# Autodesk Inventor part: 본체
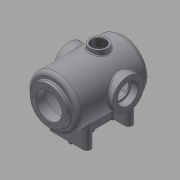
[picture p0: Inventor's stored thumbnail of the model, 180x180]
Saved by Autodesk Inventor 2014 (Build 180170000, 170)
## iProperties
Created: 2016-02
Part Number: 본체
Material: Aluminum 6061
Document SubType Name: Modeling
Designer: mduedu
Density: 2.71 g/cm^3
Appearance: Default
Mass: 3178.08 g
Surface Area: 2086.6 cm^2
Volume: 1172.72 cm^3
Author: mduedu
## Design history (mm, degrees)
sketch "스케치2"
  geometry: L1 (0, 100)-(0, -100); L2 (65, -75.993)-(65, 100); L3 (65, 100)-(0, 100); A1 r 100 centre (0, 0) between (0, -100) and (65, -75.993); 2 further points
  constraints: 6 end point, 2 midpoint, 2 point on circle, 1 centre point, 1 coincident, 1 horizontal, 1 parallel, 1 vertical
  dimensions: "d3" = 200 distance of L1.start L1.end; "d5" = 130 diameter of L2 L1; "d6" = 100 radius of A1
revolve "회전1" sketch "스케치2" stored, may be unused: angle "d7" = 90 deg
sketch "스케치3"
  geometry: C1 r 47.5 at (0, 0); 1 further point
  constraints: 1 centre point, 1 coincident
  dimensions: "d8" = 95 diameter of C1
extrude "돌출2" join sketch "스케치3" distance "d10" = 10; taper "d11" = 0 deg
sketch "스케치5"
  geometry: L1 (47.5, 110)-(47.5, 100) reference; L2 (47.5, 100)-(65, 100) reference; L3 (65, 100)-(65, -75.993) reference; L4 (-65, -75.993)-(-65, 100) reference; L5 (-65, 100)-(-47.5, 100) reference; L6 (-47.5, 100)-(-47.5, 110) reference; L7 (-47.5, 110)-(47.5, 110) reference; L8 (55, 85)-(55, -71.239); L9 (0, 85)-(55, 85); L10 (0, 85)-(0, -90); A1 r 100 centre (0, 0) between (0, -100) and (65, -75.993) reference; A2 r 100 centre (0, 0) between (-65, -75.993) and (0, -100) reference; A3 r 90 centre (0, 0) between (0, -90) and (55, -71.239); 1 further point
  constraints: 6 end point, 2 point on circle, 1 centre point, 1 parallel, 1 perpendicular, 1 point on line, 1 vertical
  dimensions: "d13" = 10 distance between parallel lines of L3 L8; "d14" = 10 radial gap between concentric circles of A3 A1; "d15" = 15 distance between parallel lines of L9 L2
revolve "회전2" sketch "스케치5" stored, may be unused: angle "d16" = 90 deg
hole "구멍1" diameter "d19" = 65; stored, may be unused: countersink angle "d23" = 90 deg, drill point angle "d25" = 118 deg; dims "d17" = 10, "d18" = 10, "d20" = 6, "d21" = 4, "d22" = 2, "d24" = 8
node "작업 평면1"
sketch "스케치6"
  geometry: L1 (47.5, 110)-(-47.5, 110) reference; C1 r 40 at (0, -17); 1 further point
  constraints: 1 centre point, 1 vertical alignment
  dimensions: "d27" = 80 diameter of C1; "d29" = 127 distance from line of C1.centre L1
extrude "돌출3" join sketch "스케치6" stored distance "d30" = 10; taper "d31" = 0 deg
hole "구멍2" diameter "d34" = 42; stored, may be unused: countersink angle "d38" = 90 deg, drill point angle "d40" = 118 deg; dims "d32" = 10, "d33" = 10, "d35" = 6, "d36" = 52, "d37" = 18, "d39" = 8
sketch "스케치7" dims "d41" = 65
  geometry: C1 r 40 at (0, 0) reference; 3 further points
  constraints: 2 vertical alignment, 1 coincident, 2 other
hole "구멍3" sketch "스케치7" at (0, 32.5) diameter "d43" = 3.242; stored, may be unused: countersink angle "d47" = 90 deg, drill point angle "d49" = 118 deg; dims "d44" = 11, "d45" = 13, "d46" = 18, "d48" = 13
sketch "스케치8" dims "d53" = 80
  geometry: 3 further points
  constraints: 2 vertical alignment, 1 coincident, 2 other
hole "구멍4" sketch "스케치8" at (0, 40) diameter "d56" = 3.242; stored, may be unused: countersink angle "d60" = 90 deg, drill point angle "d62" = 118 deg; dims "d57" = 11, "d58" = 13, "d59" = 18, "d61" = 13
fillet "모깎기1" dims "d66" = 10
fillet "모깎기2" dims "d67" = 3
fillet "모깎기3" dims "d68" = 0.3
chamfer "모따기1" distance "d69" = 1; stored, may be unused: second distance "d70" = 2, angle "d71" = 45 deg
node "작업 평면5"
sketch "스케치10"
  geometry: L1 (-50, -63)-(50, -63); L2 (50, -63)-(50, -43); L3 (50, -43)-(-50, -43); L4 (-50, -43)-(-50, -63); L5 (-50, 0)-(50, 0); L6 (-50, 63)-(50, 63); L7 (50, 63)-(50, 43); L8 (50, 43)-(-50, 43); L9 (-50, 43)-(-50, 63); 2 further points
  constraints: 18 end point, 4 symmetric about line, 2 parallel, 2 perpendicular, 1 coincident, 1 horizontal, 1 midpoint
  dimensions: "d80" = 20 distance of L3.end L1.start; "d82" = 100 distance of L1.start L1.end; "d130" = 43 vertical distance of L3.end point (0, 0); "d131" = 50 horizontal distance of L3.end point (0, 0); "d132" = 100 distance of L5.start L5.end
extrude "돌출5" join sketch "스케치10" stored distance "d84" = 10; taper "d85" = 0 deg
sketch "스케치11"
  geometry: L1 (-100, -43)-(-100, 43); L2 (-65, 90)-(-65, -71.239) reference; L3 (-100, -43)-(-41.533, -43) reference; L4 (-100, 43)-(-41.533, 43) reference; 1 further point
  constraints: 2 end point, 1 point on line, 1 vertical
feature "리브1" sketch "스케치11" dims "d88" = 1, "d89" = 20, "d90" = 0, "d91" = 0, "d92" = 1, "d93" = 1
fillet "모깎기12"
fillet "모깎기13"
fillet "모깎기14"
fillet "모깎기15"
fillet "모깎기16" dims "d167" = 3
fillet "모깎기17" dims "d168" = 3
node "작업 평면6"
sketch "스케치19"
  geometry: L1 (75, -57)-(75, 23) reference; L2 (-75, -57)-(-75, 23) reference; L3 (75, -17)-(-75, -17); C1 r 22.5 at (0, -17); 1 further point
  constraints: 3 midpoint, 2 end point, 1 centre point
  dimensions: "d149" = 45 diameter of C1
extrude "돌출11" join sketch "스케치19" stored distance "d150" = 10; taper "d151" = 0 deg
hole "구멍6" diameter "d154" = 35; stored, may be unused: countersink angle "d158" = 90 deg, drill point angle "d160" = 118 deg; dims "d152" = 10, "d153" = 10, "d155" = 6, "d156" = 4, "d157" = 2, "d159" = 8
fillet "모깎기11" dims "d161" = 3
feature "스레드1" dims "d162" = 10, "d163" = 0
chamfer "모따기3" distance "d164" = 1; stored, may be unused: second distance "d165" = 2, angle "d166" = 45 deg
sketch "스케치20"
  geometry: L1 (10, 40)-(10, -40) reference; L2 (13, -43)-(40, -43) reference; L3 (40, -63)-(-40, -63) reference; L4 (-40, -43)-(-13, -43) reference; L5 (-10, -40)-(-10, 40) reference; L6 (-13, 43)-(-40, 43) reference; L7 (-40, 63)-(40, 63) reference; L8 (40, 43)-(13, 43) reference; L9 (-40, 53)-(40, 53); L10 (-40, -53)-(40, -53); L11 (0, 53)-(0, -53); C1 r 5 at (0, 53); C2 r 5 at (0, 0); C3 r 5 at (0, -53); A1 r 3 centre (13, -40) between (10, -40) and (13, -43) reference; A2 r 10 centre (40, -53) between (40, -63) and (40, -43) reference; A3 r 10 centre (-40, -53) between (-40, -43) and (-40, -63) reference; A4 r 3 centre (-13, -40) between (-13, -43) and (-10, -40) reference; A5 r 3 centre (-13, 40) between (-10, 40) and (-13, 43) reference; A6 r 10 centre (-40, 53) between (-40, 63) and (-40, 43) reference; A7 r 10 centre (40, 53) between (40, 43) and (40, 63) reference; A8 r 3 centre (13, 40) between (13, 43) and (10, 40) reference; 1 further point
  constraints: 6 end point, 3 centre point, 3 coincident, 2 midpoint, 2 parallel
  dimensions: "d169" = 10 diameter of C1; "d170" = 10 diameter of C2; "d171" = 10 diameter of C3
extrude "돌출12" join sketch "스케치20" distance "d172" = 10; taper "d173" = 0 deg
chamfer "모따기4" distance "d174" = 1; stored, may be unused: second distance "d175" = 2, angle "d176" = 45 deg
node "솔리드2"
pattern_circular "원형 패턴1" dims angle "d51" = 360 deg
mirror "대칭1"
pattern_circular "원형 패턴2" dims angle "d64" = 360 deg
node "절단 모서리 투영1"
node "절단 모서리 투영4"
other parameters: "d26" = 75, "d136" = 175
